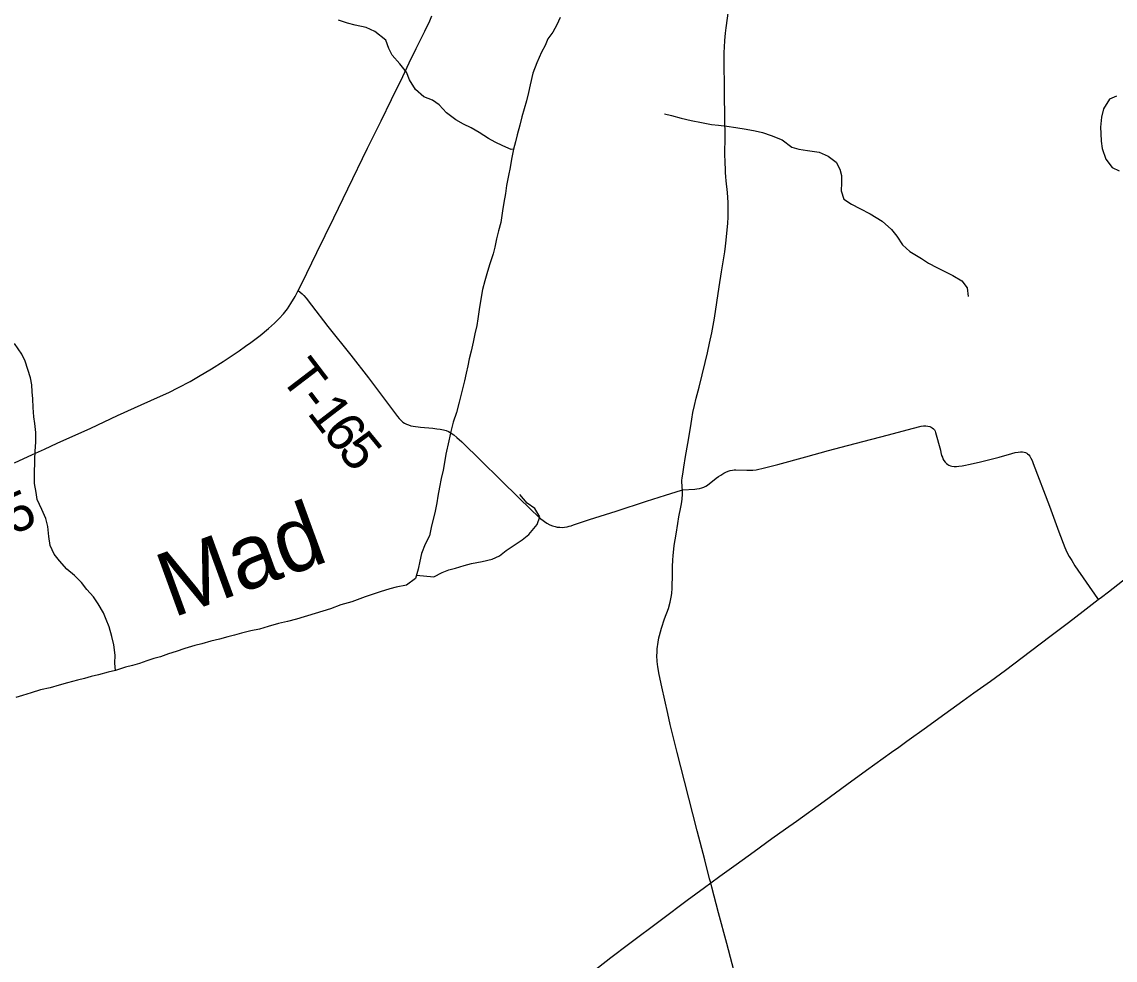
# Model space of a CAD drawing. Extents: x 0 to 1101, y 0 to 440.
# Drawn here: x 842.564 to 844.169, y 379.151 to 380.529 of the extents above; entities that cross this region are included whole.
import ezdxf

# ---------------------------------------------------------------- set-up
doc = ezdxf.new("R2010")
doc.units = 0
for name, color, linetype in [('GM_X_County_Road', 7, 'Continuous'), ('GM_X_County_Road_Text', 7, 'Continuous'), ('GM_X_Major_River', 7, 'Continuous'), ('GM_X_Major_River_Text', 7, 'Continuous'), ('GM_X_Minor_River', 7, 'Continuous'), ('GM_X_Township_Road', 7, 'Continuous'), ('GM_X_Township_Road_Text', 7, 'Continuous')]:
    doc.layers.add(name, color=color, linetype=linetype)

msp = doc.modelspace()

# ---------------------------------------------------------------- linework, layer by layer
at = {"layer": 'GM_X_County_Road'}
for points in [[(842.5532, 379.8816), (842.5798, 379.8935), (842.5974, 379.9015), (842.616, 379.9101), (842.6652, 379.9325), (842.7046, 379.9509), (842.7295, 379.9622), (842.7629, 379.9773), (842.7799, 379.9849), (842.7939, 379.9918), (842.8109, 380.0009), (842.8232, 380.0081), (842.8423, 380.0193), (842.8597, 380.0303), (842.883, 380.046), (842.8921, 380.0525), (842.9002, 380.0583), (842.9136, 380.0684), (842.9262, 380.0786), (842.9351, 380.0865), (842.9417, 380.0931), (842.948, 380.1001), (842.9537, 380.1075), (842.959, 380.1152), (842.965, 380.1255), (842.9696, 380.1342), (842.9734, 380.1415), (842.9824, 380.1599), (842.9971, 380.19), (843.0094, 380.2152), (843.0219, 380.2409), (843.0427, 380.2837), (843.0716, 380.3431), (843.0915, 380.3832), (843.1066, 380.4145), (843.1231, 380.4487), (843.1328, 380.4688), (843.1428, 380.4895), (843.1477, 380.4995), (843.1554, 380.5151), (843.1571, 380.5184), (843.1617, 380.528), (843.1659, 380.5377)], [(843.3992, 379.1325), (843.4288, 379.1552), (843.4545, 379.1748), (843.5032, 379.2113), (843.5409, 379.2397), (843.5659, 379.2581), (843.5752, 379.2648), (843.5885, 379.2745), (843.6126, 379.2921), (843.6389, 379.3109), (843.665, 379.3298), (843.6851, 379.3443), (843.7013, 379.3557), (843.7416, 379.385), (843.775, 379.4091), (843.8042, 379.4302), (843.8408, 379.4566), (843.8513, 379.4642), (843.8634, 379.4729), (843.8921, 379.4934), (843.9102, 379.5065), (843.9452, 379.532), (843.9613, 379.5436), (843.986, 379.5612), (844.0078, 379.5771), (844.0326, 379.5955), (844.0733, 379.6265), (844.1005, 379.6473), (844.1218, 379.6635), (844.1442, 379.6807), (844.1489, 379.6843), (844.1592, 379.6923), (844.1867, 379.7136)]]:
    msp.add_lwpolyline(points, dxfattribs=at)
at = {"layer": 'GM_X_Major_River'}
for points in [[(843.3543, 380.5349), (843.3492, 380.5243), (843.3434, 380.5138), (843.336, 380.504), (843.3321, 380.4942), (843.3267, 380.484), (843.32, 380.4686), (843.3141, 380.4535), (843.3101, 380.4361), (843.3077, 380.4251), (843.3049, 380.413), (843.3013, 380.4009), (843.2981, 380.3895), (843.2949, 380.3771), (843.2909, 380.3631), (843.2885, 380.3528), (843.2857, 380.3419), (843.2828, 380.3271), (843.2808, 380.315), (843.2783, 380.3033), (843.2755, 380.2885), (843.2738, 380.2768), (843.2713, 380.2635), (843.2696, 380.2514), (843.2671, 380.2343), (843.2639, 380.2219), (843.2607, 380.2101), (843.2583, 380.198), (843.2559, 380.1882), (843.2504, 380.1723), (843.2464, 380.1587), (843.2436, 380.1485), (843.2404, 380.136), (843.2379, 380.1216), (843.2354, 380.1065), (843.2333, 380.0929), (843.2317, 380.083), (843.2292, 380.0709), (843.2264, 380.0584), (843.2236, 380.0452), (843.2208, 380.0342), (843.2187, 380.0236), (843.2163, 380.013), (843.2139, 380.002), (843.2115, 379.9918), (843.209, 379.982), (843.2062, 379.9706), (843.2022, 379.9555), (843.1971, 379.9412), (843.1935, 379.9276), (843.191, 379.9136), (843.1866, 379.8943), (843.1845, 379.8821), (843.1825, 379.8708), (843.1796, 379.8583), (843.1772, 379.8458), (843.1744, 379.8326), (843.1731, 379.8227), (843.1706, 379.8106), (843.165, 379.7864), (843.1626, 379.7743)], [(843.1626, 379.7743), (843.1559, 379.7622), (843.1508, 379.7483), (843.148, 379.7369), (843.1456, 379.7252), (843.142, 379.7116), (843.1286, 379.7019), (843.1137, 379.6987), (843.1042, 379.6965), (843.0902, 379.6922), (843.078, 379.6882), (843.0681, 379.6849), (843.0483, 379.6776), (843.0323, 379.6729), (843.017, 379.667), (843.0056, 379.6638), (842.9946, 379.6605), (842.9672, 379.6518), (842.9539, 379.6485), (842.9406, 379.6457), (842.9257, 379.641), (842.9128, 379.6373), (842.9002, 379.6349), (842.8862, 379.6313), (842.8759, 379.6284), (842.8664, 379.6262), (842.8542, 379.6226), (842.8413, 379.6198), (842.828, 379.6158), (842.8181, 379.6132), (842.8032, 379.6089), (842.7903, 379.6045), (842.7793, 379.6013), (842.7674, 379.5969), (842.7576, 379.5944), (842.7473, 379.5907), (842.7366, 379.5871), (842.7263, 379.5842), (842.7161, 379.5817), (842.7012, 379.5765), (842.6909, 379.574), (842.6765, 379.5701), (842.6655, 379.5676), (842.6559, 379.5647), (842.6457, 379.5625), (842.6308, 379.5586), (842.6187, 379.5549), (842.6057, 379.5513), (842.5913, 379.5481), (842.5776, 379.5437), (842.565, 379.5398), (842.5551, 379.5369)]]:
    msp.add_lwpolyline(points, dxfattribs=at)
at = {"layer": 'GM_X_Minor_River'}
for points in [[(843.2857, 380.3419), (843.2823, 380.3412), (843.2702, 380.3466), (843.2589, 380.3521), (843.2491, 380.3576), (843.2352, 380.3665), (843.2236, 380.3731), (843.2123, 380.3786), (843.201, 380.3848), (843.1875, 380.3952), (843.1767, 380.4071), (843.1669, 380.4137), (843.1541, 380.4188), (843.1418, 380.4296), (843.1332, 380.4434), (843.1288, 380.4549), (843.1188, 380.4672), (843.1076, 380.4798), (843.1028, 380.4898), (843.0984, 380.5016), (843.0823, 380.5147), (843.0695, 380.5206), (843.0532, 380.5239), (843.0419, 380.5267), (843.0287, 380.5314)], [(844.1712, 380.4198), (844.1605, 380.4154), (844.152, 380.401), (844.1492, 380.3886), (844.1475, 380.3742), (844.1481, 380.3647), (844.1483, 380.3537), (844.1501, 380.343), (844.1552, 380.327), (844.1648, 380.3151), (844.175, 380.31)], [(843.5073, 380.3935), (843.5179, 380.3911), (843.5319, 380.3875), (843.5466, 380.3839), (843.5617, 380.381), (843.5765, 380.3781), (843.5867, 380.3769), (843.5988, 380.3755), (843.612, 380.3735), (843.6275, 380.3714), (843.6407, 380.3689), (843.6513, 380.3665), (843.6641, 380.3621), (843.68, 380.3555), (843.6942, 380.345), (843.7044, 380.3418), (843.7173, 380.3398), (843.7347, 380.3373), (843.7479, 380.3318), (843.7595, 380.3229), (843.7646, 380.3126), (843.7672, 380.303), (843.7674, 380.2924), (843.7668, 380.2806), (843.7708, 380.2684), (843.7817, 380.2611), (843.7942, 380.2548), (843.8092, 380.247), (843.8269, 380.2362), (843.8407, 380.2238), (843.8485, 380.2139), (843.8567, 380.2016), (843.8675, 380.1916), (843.8848, 380.1815), (843.895, 380.1745), (843.9074, 380.1683), (843.9307, 380.1566), (843.9439, 380.1484), (843.9517, 380.1381), (843.9534, 380.1255)], [(842.7012, 379.5765), (842.7006, 379.5872), (842.7008, 379.5993), (842.6991, 379.6145), (842.6959, 379.6267), (842.6919, 379.6408), (842.6879, 379.6515), (842.6838, 379.6614), (842.6761, 379.6744), (842.669, 379.6848), (842.6593, 379.6955), (842.6515, 379.7059), (842.6414, 379.7159), (842.6298, 379.7252), (842.6193, 379.7374), (842.6115, 379.7474), (842.6056, 379.76), (842.6036, 379.7733), (842.6022, 379.7882), (842.5994, 379.7996), (842.5935, 379.8129), (842.5865, 379.8278), (842.5848, 379.8381), (842.5827, 379.851), (842.5825, 379.8628), (842.5828, 379.8867), (842.5837, 379.8981), (842.5843, 379.9125), (842.5845, 379.9261), (842.5828, 379.9391), (842.5814, 379.949), (842.5808, 379.9626), (842.5802, 379.9752), (842.5792, 379.9858), (842.5786, 379.9957), (842.5765, 380.0063), (842.5729, 380.0185), (842.5689, 380.0307), (842.5641, 380.0407), (842.5533, 380.0567)], [(843.1433, 379.7165), (843.1689, 379.7142), (843.1811, 379.7205), (843.191, 379.7246), (843.2005, 379.7267), (843.2135, 379.7307), (843.2241, 379.7336), (843.2397, 379.7368), (843.2542, 379.74), (843.2652, 379.7448), (843.2748, 379.7526), (843.2882, 379.7616), (843.2985, 379.7682), (843.3081, 379.7761), (843.3204, 379.7907), (843.3244, 379.802), (843.317, 379.8143), (843.3057, 379.8224), (843.2949, 379.8351)]]:
    msp.add_lwpolyline(points, dxfattribs=at)
at = {"layer": 'GM_X_Township_Road'}
for points in [[(843.6148, 379.1161), (843.5988, 379.1761), (843.5866, 379.2211), (843.5768, 379.2584), (843.5752, 379.2648), (843.5737, 379.2706), (843.5665, 379.2987), (843.5553, 379.3414), (843.5368, 379.4142), (843.526, 379.4564), (843.5193, 379.4835), (843.5159, 379.4974), (843.5121, 379.5137), (843.5037, 379.5528), (843.4995, 379.5707), (843.4974, 379.582), (843.4965, 379.59), (843.496, 379.5986), (843.4964, 379.6031), (843.4967, 379.6082), (843.4979, 379.6181), (843.4992, 379.6247), (843.4999, 379.6279), (843.5028, 379.6388), (843.5074, 379.6524), (843.5134, 379.6677), (843.5158, 379.6767), (843.5173, 379.6843), (843.5181, 379.6898), (843.5187, 379.6975), (843.5187, 379.7033), (843.519, 379.7125), (843.5191, 379.7232), (843.5193, 379.7287), (843.5198, 379.7391), (843.5203, 379.7451), (843.5218, 379.7599), (843.5243, 379.7765), (843.5268, 379.7924), (843.5285, 379.802), (843.5316, 379.8162), (843.5326, 379.8214), (843.5335, 379.8282), (843.5338, 379.8353), (843.5336, 379.8416), (843.5335, 379.8453), (843.5333, 379.8487), (843.5329, 379.8522), (843.5329, 379.8558), (843.5333, 379.8591), (843.5348, 379.8682), (843.5359, 379.875), (843.5384, 379.8909), (843.5418, 379.9099), (843.5455, 379.9326), (843.5475, 379.9455), (843.5491, 379.9553), (843.5513, 379.9656), (843.5539, 379.9765), (843.5583, 379.9927), (843.5672, 380.0288), (843.5704, 380.0427), (843.5737, 380.0572), (843.5768, 380.0724), (843.5806, 380.0938), (843.5878, 380.1398), (843.5912, 380.1619), (843.5959, 380.1912), (843.597, 380.1993), (843.598, 380.2083), (843.599, 380.2185), (843.6006, 380.2329), (843.601, 380.2424), (843.601, 380.2486), (843.601, 380.2566), (843.6008, 380.2634), (843.5998, 380.2782), (843.598, 380.2955), (843.5974, 380.3011), (843.597, 380.3078), (843.5968, 380.3136), (843.5965, 380.3206), (843.5961, 380.3365), (843.5963, 380.3582), (843.5956, 380.4216), (843.5954, 380.4353), (843.5951, 380.4657), (843.5952, 380.4837), (843.5953, 380.4918), (843.5959, 380.5015), (843.597, 380.5121), (843.598, 380.5197), (843.6014, 380.545)], [(842.9696, 380.1342), (842.9724, 380.1318), (842.9753, 380.1294), (842.9781, 380.127), (842.9812, 380.1231), (842.9893, 380.1127), (843.0132, 380.0817), (843.0469, 380.0393), (843.0728, 380.006), (843.1156, 379.9494), (843.1181, 379.9465), (843.1208, 379.9436), (843.1234, 379.9413), (843.1257, 379.9397), (843.1284, 379.9383), (843.1315, 379.937), (843.1349, 379.9359), (843.1385, 379.9351), (843.1492, 379.9338), (843.1673, 379.9322), (843.1732, 379.9315), (843.1782, 379.9307), (843.1832, 379.9298), (843.1867, 379.9287), (843.1901, 379.9273), (843.1942, 379.9248), (843.198, 379.9223), (843.2024, 379.9187), (843.2097, 379.9121), (843.2947, 379.8292), (843.3241, 379.8006), (843.3311, 379.7951), (843.3348, 379.7928), (843.3393, 379.7905), (843.343, 379.789), (843.3467, 379.7879), (843.3499, 379.7872), (843.3537, 379.7868), (843.3571, 379.7867), (843.3608, 379.7871), (843.3643, 379.7876), (843.3674, 379.7883), (843.3702, 379.7891), (843.374, 379.7904), (843.3973, 379.7981), (843.4363, 379.8107), (843.4812, 379.8254), (843.5089, 379.8342), (843.5325, 379.8412), (843.5336, 379.8416)], [(843.5336, 379.8416), (843.5517, 379.843), (843.5551, 379.8433), (843.5588, 379.8439), (843.562, 379.8447), (843.565, 379.8456), (843.568, 379.8472), (843.5706, 379.8488), (843.5833, 379.8588), (843.5868, 379.8613), (843.5901, 379.8635), (843.5946, 379.8661), (843.5974, 379.8676), (843.601, 379.8692), (843.604, 379.8702), (843.6072, 379.8709), (843.6095, 379.8712), (843.6123, 379.8713), (843.6282, 379.8707), (843.6322, 379.8707), (843.6369, 379.8709), (843.6418, 379.8713), (843.6457, 379.872), (843.6502, 379.8729), (843.674, 379.8791), (843.7147, 379.8902), (843.7483, 379.8994), (843.7759, 379.9067), (843.8118, 379.9161), (843.8362, 379.9223), (843.8711, 379.9317), (843.8844, 379.9351), (843.8874, 379.9356), (843.8909, 379.9358), (843.8941, 379.9354), (843.8971, 379.9348), (843.899, 379.9338), (843.9006, 379.933), (843.9025, 379.9313), (843.9037, 379.9298), (843.9047, 379.9279), (843.9052, 379.9261), (843.9125, 379.8998), (843.9132, 379.8968), (843.9143, 379.8924), (843.9153, 379.8898), (843.9162, 379.8874), (843.9176, 379.885), (843.9196, 379.8823), (843.9214, 379.8805), (843.9233, 379.8789), (843.925, 379.8779), (843.9271, 379.877), (843.9294, 379.8764), (843.9326, 379.876), (843.9361, 379.8762), (843.9395, 379.8765), (843.9442, 379.8772), (843.9491, 379.8781), (843.9536, 379.879), (843.9694, 379.8826), (843.9989, 379.89), (844.0174, 379.8953), (844.022, 379.8965), (844.0264, 379.8973), (844.0299, 379.8976), (844.0329, 379.8974), (844.0353, 379.8972), (844.0375, 379.8965), (844.0391, 379.8957), (844.0405, 379.8948), (844.0422, 379.8932), (844.0437, 379.8914), (844.0452, 379.8885), (844.047, 379.8847), (844.0487, 379.8805), (844.0724, 379.8176), (844.0862, 379.7803), (844.0952, 379.757), (844.0982, 379.7505), (844.1015, 379.7441), (844.1053, 379.7379), (844.11, 379.7303), (844.1431, 379.6822), (844.1442, 379.6807)]]:
    msp.add_lwpolyline(points, dxfattribs=at)

# ---------------------------------------------------------------- texts
at = {"layer": 'GM_X_County_Road_Text'}
msp.add_text('C-5', height=0.05682, rotation=24.1028, dxfattribs=at).set_placement((842.478, 379.7426))
at = {"layer": 'GM_X_Major_River_Text'}
msp.add_text('Mad', height=0.0947, rotation=20.028, dxfattribs=at).set_placement((842.7854, 379.6537))
at = {"layer": 'GM_X_Township_Road_Text'}
for s, rotation, p in [('T', 307.3405, (842.9418, 380.007)), ('-', 307.3673, (842.9675, 379.9732)), ('1', 307.5273, (842.9818, 379.9545)), ('6', 308.0375, (843.0035, 379.9263)), ('5', 309.4294, (843.026, 379.8976))]:
    msp.add_text(s, height=0.0568, rotation=rotation, dxfattribs=at).set_placement(p)

doc.saveas('drawing.dxf')
